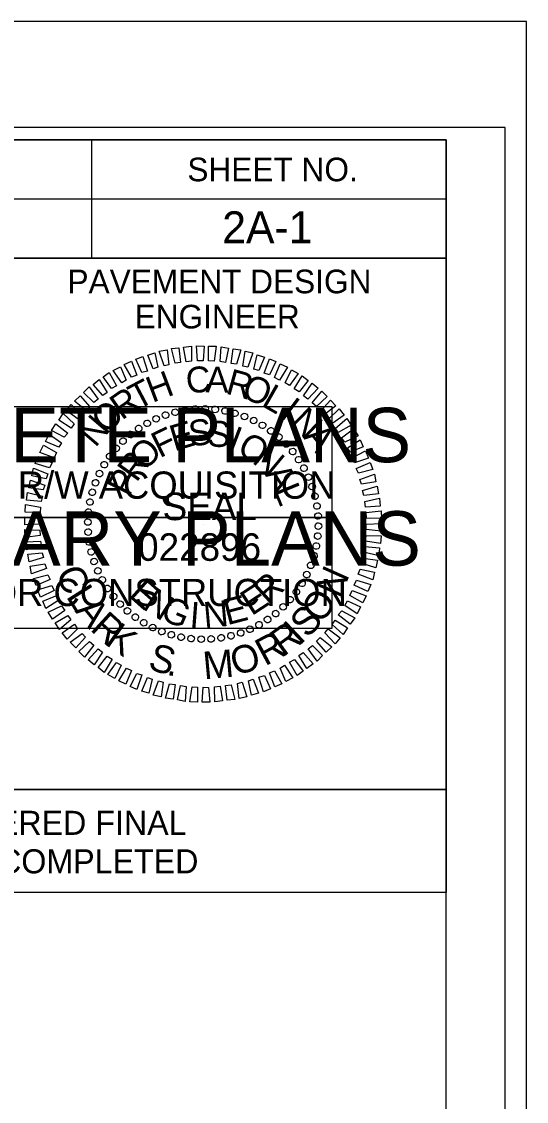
# Model space of a CAD drawing. Extents: x 1734085 to 1734267, y 541107 to 541226.
# Drawn here: x 1734254.98 to 1734266.51, y 541201.19 to 541225.88 of the extents above; entities that cross this region are included whole.
import ezdxf

# ---------------------------------------------------------------- set-up
doc = ezdxf.new("R2010")
doc.units = 0
for name, color, linetype in [('Sheet Cutting Line CELL', 7, 'Continuous'), ('Sheet Data Field CELL', 7, 'Continuous'), ('Sheet PE Seal Cell', 7, 'Continuous'), ('Sheet Plot Border Inside CELL', 7, 'Continuous'), ('Sheet Plot Border Outside CELL', 7, 'Continuous'), ('Sheet Sticker Exception Certification CELL', 7, 'Continuous'), ('Sheet Sticker Incomplete CELL', 7, 'Continuous'), ('Sheet Sticker Preliminary CELL', 7, 'Continuous'), ('Sheet Typical CELL', 7, 'Continuous')]:
    doc.layers.add(name, color=color, linetype=linetype)

msp = doc.modelspace()

# ---------------------------------------------------------------- linework, layer by layer
at = {"layer": 'Sheet Cutting Line CELL'}
msp.add_line((1734266.513, 541225.875), (1734084.641, 541225.875), dxfattribs=at)
at = {"layer": 'Sheet PE Seal Cell'}
for p, q in [((1734258.267, 541216.884), (1734258.267, 541216.884)), ((1734258.488, 541216.947), (1734258.488, 541216.947)), ((1734258.719, 541216.989), (1734258.719, 541216.989)), ((1734258.945, 541217.02), (1734258.945, 541217.02)), ((1734259.176, 541217.025), (1734259.176, 541217.025)), ((1734259.407, 541217.01), (1734259.407, 541217.01)), ((1734259.632, 541216.973), (1734259.632, 541216.973)), ((1734259.853, 541216.926), (1734259.853, 541216.926)), ((1734257.853, 541216.695), (1734257.853, 541216.695)), ((1734258.057, 541216.8), (1734258.057, 541216.8)), ((1734260.073, 541216.852), (1734260.073, 541216.852)), ((1734260.283, 541216.758), (1734260.283, 541216.758)), ((1734260.488, 541216.653), (1734260.488, 541216.653)), ((1734257.469, 541216.443), (1734257.469, 541216.443)), ((1734257.653, 541216.574), (1734257.653, 541216.574)), ((1734260.677, 541216.521), (1734260.677, 541216.521)), ((1734260.861, 541216.38), (1734260.861, 541216.38)), ((1734257.139, 541216.122), (1734257.139, 541216.122)), ((1734257.296, 541216.285), (1734257.296, 541216.285)), ((1734261.024, 541216.222), (1734261.024, 541216.222)), ((1734256.997, 541215.939), (1734256.997, 541215.939)), ((1734261.181, 541216.049), (1734261.181, 541216.049)), ((1734256.866, 541215.75), (1734256.866, 541215.75)), ((1734261.312, 541215.865), (1734261.312, 541215.865)), ((1734261.433, 541215.666), (1734261.433, 541215.666)), ((1734256.761, 541215.545), (1734256.761, 541215.545)), ((1734261.538, 541215.461), (1734261.538, 541215.461)), ((1734256.666, 541215.335), (1734256.666, 541215.335)), ((1734261.622, 541215.251), (1734261.622, 541215.251)), ((1734256.545, 541214.894), (1734256.545, 541214.894)), ((1734256.593, 541215.114), (1734256.593, 541215.114)), ((1734261.685, 541215.03), (1734261.685, 541215.03)), ((1734256.509, 541214.668), (1734256.509, 541214.668)), ((1734261.727, 541214.799), (1734261.727, 541214.799)), ((1734256.493, 541214.437), (1734256.493, 541214.437)), ((1734261.759, 541214.574), (1734261.759, 541214.574)), ((1734256.498, 541214.206), (1734256.498, 541214.206)), ((1734259.128, 541214.39), (1734259.128, 541214.39)), ((1734261.764, 541214.343), (1734261.764, 541214.343)), ((1734256.53, 541213.98), (1734256.53, 541213.98)), ((1734261.748, 541214.112), (1734261.748, 541214.112)), ((1734256.572, 541213.749), (1734256.572, 541213.749)), ((1734261.664, 541213.665), (1734261.664, 541213.665)), ((1734261.711, 541213.886), (1734261.711, 541213.886)), ((1734256.635, 541213.529), (1734256.635, 541213.529)), ((1734261.591, 541213.445), (1734261.591, 541213.445)), ((1734256.719, 541213.319), (1734256.719, 541213.319)), ((1734261.496, 541213.235), (1734261.496, 541213.235)), ((1734256.824, 541213.114), (1734256.824, 541213.114)), ((1734256.944, 541212.915), (1734256.944, 541212.915)), ((1734261.391, 541213.03), (1734261.391, 541213.03)), ((1734257.076, 541212.731), (1734257.076, 541212.731)), ((1734261.26, 541212.841), (1734261.26, 541212.841)), ((1734257.233, 541212.558), (1734257.233, 541212.558)), ((1734260.961, 541212.495), (1734260.961, 541212.495)), ((1734261.118, 541212.657), (1734261.118, 541212.657)), ((1734257.396, 541212.4), (1734257.396, 541212.4)), ((1734257.58, 541212.258), (1734257.58, 541212.258)), ((1734260.604, 541212.206), (1734260.604, 541212.206)), ((1734260.787, 541212.337), (1734260.787, 541212.337)), ((1734257.769, 541212.127), (1734257.769, 541212.127)), ((1734257.973, 541212.022), (1734257.973, 541212.022)), ((1734258.183, 541211.928), (1734258.183, 541211.928)), ((1734260.199, 541211.98), (1734260.199, 541211.98)), ((1734260.404, 541212.085), (1734260.404, 541212.085)), ((1734258.404, 541211.854), (1734258.404, 541211.854)), ((1734258.624, 541211.807), (1734258.624, 541211.807)), ((1734258.85, 541211.77), (1734258.85, 541211.77)), ((1734259.081, 541211.754), (1734259.081, 541211.754)), ((1734259.312, 541211.76), (1734259.312, 541211.76)), ((1734259.538, 541211.791), (1734259.538, 541211.791)), ((1734259.769, 541211.833), (1734259.769, 541211.833)), ((1734259.989, 541211.896), (1734259.989, 541211.896))]:
    msp.add_line(p, q, dxfattribs=at)
for points in [[(1734258.236, 541218.007), (1734258.126, 541218.338), (1734258.304, 541218.375), (1734258.346, 541218.033)], [(1734258.488, 541218.065), (1734258.404, 541218.401), (1734258.577, 541218.417), (1734258.614, 541218.081)], [(1734258.74, 541218.096), (1734258.682, 541218.432), (1734258.861, 541218.453), (1734258.866, 541218.112)], [(1734259.002, 541218.123), (1734258.976, 541218.464), (1734259.149, 541218.459), (1734259.128, 541218.117)], [(1734259.254, 541218.117), (1734259.254, 541218.459), (1734259.428, 541218.453), (1734259.38, 541218.112)], [(1734259.517, 541218.102), (1734259.538, 541218.443), (1734259.711, 541218.411), (1734259.643, 541218.081)], [(1734259.769, 541218.06), (1734259.816, 541218.396), (1734259.989, 541218.369), (1734259.895, 541218.044)], [(1734260.037, 541218.002), (1734260.089, 541218.343), (1734260.268, 541218.301), (1734260.147, 541217.976)], [(1734257.496, 541217.745), (1734257.328, 541218.039), (1734257.49, 541218.112), (1734257.611, 541217.792)], [(1734257.727, 541217.855), (1734257.59, 541218.159), (1734257.748, 541218.222), (1734257.858, 541217.886)], [(1734257.984, 541217.939), (1734257.863, 541218.254), (1734258.026, 541218.301), (1734258.094, 541217.976)], [(1734260.289, 541217.934), (1734260.367, 541218.259), (1734260.53, 541218.207), (1734260.399, 541217.897)], [(1734260.525, 541217.839), (1734260.646, 541218.17), (1734260.793, 541218.107), (1734260.646, 541217.802)], [(1734257.039, 541217.487), (1734256.845, 541217.755), (1734256.981, 541217.855), (1734257.154, 541217.55)], [(1734257.27, 541217.619), (1734257.076, 541217.902), (1734257.238, 541217.986), (1734257.37, 541217.682)], [(1734260.761, 541217.739), (1734260.892, 541218.049), (1734261.055, 541217.976), (1734260.877, 541217.682)], [(1734261.003, 541217.619), (1734261.144, 541217.918), (1734261.302, 541217.829), (1734261.102, 541217.556)], [(1734256.839, 541217.33), (1734256.614, 541217.582), (1734256.755, 541217.692), (1734256.939, 541217.398)], [(1734261.207, 541217.477), (1734261.391, 541217.781), (1734261.528, 541217.671), (1734261.323, 541217.414)], [(1734261.423, 541217.319), (1734261.617, 541217.608), (1734261.753, 541217.493), (1734261.522, 541217.246)], [(1734256.629, 541217.167), (1734256.398, 541217.398), (1734256.524, 541217.524), (1734256.729, 541217.241)], [(1734261.622, 541217.157), (1734261.837, 541217.43), (1734261.963, 541217.304), (1734261.722, 541217.078)], [(1734256.272, 541216.784), (1734255.999, 541216.989), (1734256.115, 541217.125), (1734256.346, 541216.878)], [(1734256.456, 541216.983), (1734256.188, 541217.199), (1734256.32, 541217.319), (1734256.54, 541217.067)], [(1734261.811, 541216.973), (1734262.037, 541217.22), (1734262.163, 541217.094), (1734261.89, 541216.889)], [(1734256.115, 541216.584), (1734255.831, 541216.763), (1734255.931, 541216.915), (1734256.183, 541216.684)], [(1734261.995, 541216.784), (1734262.236, 541217.02), (1734262.347, 541216.878), (1734262.068, 541216.679)], [(1734255.957, 541216.374), (1734255.663, 541216.532), (1734255.768, 541216.679), (1734256.041, 541216.469)], [(1734262.152, 541216.579), (1734262.41, 541216.8), (1734262.509, 541216.647), (1734262.215, 541216.479)], [(1734255.831, 541216.149), (1734255.532, 541216.28), (1734255.611, 541216.443), (1734255.894, 541216.248)], [(1734262.289, 541216.364), (1734262.567, 541216.563), (1734262.667, 541216.406), (1734262.362, 541216.259)], [(1734255.726, 541215.907), (1734255.401, 541216.028), (1734255.48, 541216.191), (1734255.779, 541216.023)], [(1734262.425, 541216.133), (1734262.719, 541216.317), (1734262.788, 541216.154), (1734262.488, 541216.033)], [(1734255.621, 541215.676), (1734255.296, 541215.771), (1734255.364, 541215.933), (1734255.679, 541215.786)], [(1734262.53, 541215.907), (1734262.84, 541216.065), (1734262.908, 541215.897), (1734262.583, 541215.792)], [(1734255.543, 541215.424), (1734255.217, 541215.492), (1734255.254, 541215.666), (1734255.585, 541215.534)], [(1734262.625, 541215.66), (1734262.945, 541215.797), (1734263.003, 541215.634), (1734262.677, 541215.55)], [(1734255.474, 541215.172), (1734255.149, 541215.214), (1734255.186, 541215.393), (1734255.516, 541215.282)], [(1734262.709, 541215.408), (1734263.045, 541215.529), (1734263.076, 541215.356), (1734262.746, 541215.298)], [(1734262.772, 541215.156), (1734263.103, 541215.256), (1734263.134, 541215.078), (1734262.803, 541215.046)], [(1734255.432, 541214.904), (1734255.096, 541214.936), (1734255.117, 541215.114), (1734255.459, 541215.03)], [(1734262.819, 541214.904), (1734263.16, 541214.978), (1734263.176, 541214.799), (1734262.84, 541214.778)], [(1734255.406, 541214.652), (1734255.065, 541214.663), (1734255.075, 541214.836), (1734255.417, 541214.778)], [(1734262.851, 541214.652), (1734263.192, 541214.694), (1734263.202, 541214.516), (1734262.861, 541214.526)], [(1734255.401, 541214.39), (1734255.06, 541214.374), (1734255.06, 541214.553), (1734255.401, 541214.516)], [(1734262.856, 541214.39), (1734263.197, 541214.406), (1734263.197, 541214.227), (1734262.856, 541214.264)], [(1734255.406, 541214.127), (1734255.065, 541214.085), (1734255.054, 541214.264), (1734255.396, 541214.253)], [(1734255.438, 541213.875), (1734255.096, 541213.802), (1734255.081, 541213.98), (1734255.417, 541214.001)], [(1734262.851, 541214.127), (1734263.192, 541214.117), (1734263.181, 541213.944), (1734262.84, 541214.001)], [(1734255.485, 541213.623), (1734255.154, 541213.524), (1734255.123, 541213.702), (1734255.453, 541213.734)], [(1734262.824, 541213.875), (1734263.16, 541213.844), (1734263.139, 541213.665), (1734262.798, 541213.749)], [(1734255.548, 541213.371), (1734255.212, 541213.251), (1734255.18, 541213.424), (1734255.511, 541213.482)], [(1734262.782, 541213.608), (1734263.108, 541213.566), (1734263.071, 541213.387), (1734262.74, 541213.497)], [(1734255.632, 541213.119), (1734255.312, 541212.983), (1734255.254, 541213.146), (1734255.579, 541213.23)], [(1734262.714, 541213.356), (1734263.04, 541213.287), (1734263.003, 541213.114), (1734262.672, 541213.245)], [(1734255.726, 541212.873), (1734255.417, 541212.715), (1734255.348, 541212.883), (1734255.674, 541212.988)], [(1734262.635, 541213.104), (1734262.961, 541213.009), (1734262.893, 541212.846), (1734262.578, 541212.993)], [(1734255.831, 541212.647), (1734255.537, 541212.463), (1734255.469, 541212.626), (1734255.768, 541212.747)], [(1734262.53, 541212.873), (1734262.856, 541212.752), (1734262.777, 541212.589), (1734262.478, 541212.757)], [(1734255.968, 541212.416), (1734255.69, 541212.216), (1734255.59, 541212.374), (1734255.894, 541212.521)], [(1734262.425, 541212.631), (1734262.725, 541212.5), (1734262.646, 541212.337), (1734262.362, 541212.531)], [(1734256.104, 541212.201), (1734255.847, 541211.98), (1734255.747, 541212.132), (1734256.041, 541212.3)], [(1734262.142, 541212.195), (1734262.425, 541212.017), (1734262.326, 541211.865), (1734262.074, 541212.096)], [(1734262.299, 541212.405), (1734262.593, 541212.248), (1734262.488, 541212.101), (1734262.215, 541212.311)], [(1734256.262, 541211.996), (1734256.02, 541211.76), (1734255.91, 541211.901), (1734256.188, 541212.101)], [(1734261.984, 541211.996), (1734262.257, 541211.791), (1734262.142, 541211.655), (1734261.911, 541211.901)], [(1734256.446, 541211.807), (1734256.22, 541211.56), (1734256.094, 541211.686), (1734256.367, 541211.891)], [(1734256.635, 541211.623), (1734256.419, 541211.35), (1734256.293, 541211.476), (1734256.535, 541211.702)], [(1734261.801, 541211.796), (1734262.068, 541211.581), (1734261.937, 541211.46), (1734261.717, 541211.712)], [(1734256.834, 541211.46), (1734256.64, 541211.172), (1734256.503, 541211.287), (1734256.734, 541211.534)], [(1734261.417, 541211.45), (1734261.643, 541211.198), (1734261.501, 541211.088), (1734261.318, 541211.382)], [(1734261.627, 541211.613), (1734261.858, 541211.382), (1734261.732, 541211.256), (1734261.528, 541211.539)], [(1734257.049, 541211.303), (1734256.866, 541210.998), (1734256.729, 541211.109), (1734256.934, 541211.366)], [(1734257.254, 541211.161), (1734257.112, 541210.862), (1734256.955, 541210.951), (1734257.154, 541211.224)], [(1734261.218, 541211.292), (1734261.412, 541211.025), (1734261.276, 541210.925), (1734261.102, 541211.229)], [(1734257.496, 541211.04), (1734257.364, 541210.731), (1734257.202, 541210.804), (1734257.38, 541211.098)], [(1734257.732, 541210.941), (1734257.611, 541210.61), (1734257.464, 541210.673), (1734257.611, 541210.977)], [(1734260.761, 541211.035), (1734260.929, 541210.741), (1734260.766, 541210.668), (1734260.646, 541210.988)], [(1734260.987, 541211.161), (1734261.181, 541210.878), (1734261.018, 541210.794), (1734260.887, 541211.098)], [(1734257.968, 541210.846), (1734257.889, 541210.521), (1734257.727, 541210.573), (1734257.858, 541210.883)], [(1734258.22, 541210.778), (1734258.168, 541210.437), (1734257.989, 541210.479), (1734258.11, 541210.804)], [(1734258.488, 541210.72), (1734258.441, 541210.384), (1734258.267, 541210.41), (1734258.362, 541210.736)], [(1734258.74, 541210.678), (1734258.719, 541210.337), (1734258.546, 541210.368), (1734258.614, 541210.699)], [(1734259.769, 541210.715), (1734259.853, 541210.379), (1734259.68, 541210.363), (1734259.643, 541210.699)], [(1734260.021, 541210.773), (1734260.131, 541210.442), (1734259.953, 541210.405), (1734259.911, 541210.746)], [(1734260.273, 541210.841), (1734260.394, 541210.526), (1734260.231, 541210.479), (1734260.163, 541210.804)], [(1734260.53, 541210.925), (1734260.667, 541210.62), (1734260.509, 541210.557), (1734260.399, 541210.893)], [(1734259.002, 541210.662), (1734259.002, 541210.321), (1734258.829, 541210.326), (1734258.876, 541210.668)], [(1734259.254, 541210.657), (1734259.281, 541210.316), (1734259.107, 541210.321), (1734259.128, 541210.662)], [(1734259.517, 541210.683), (1734259.575, 541210.347), (1734259.396, 541210.326), (1734259.391, 541210.668)]]:
    msp.add_lwpolyline(points, close=True, dxfattribs=at)
for centre, major_axis in [((1734258.057, 541216.796), (-0.0307, 0.0691)), ((1734258.271, 541216.88), (-0.0246, 0.0715)), ((1734258.491, 541216.945), (-0.0183, 0.0734)), ((1734258.716, 541216.991), (-0.0118, 0.0747)), ((1734258.945, 541217.017), (-0.0053, 0.0754)), ((1734259.174, 541217.023), (0.0013, 0.0756)), ((1734259.404, 541217.009), (0.0079, 0.0752)), ((1734259.631, 541216.975), (0.0144, 0.0742)), ((1734259.854, 541216.921), (0.0208, 0.0727)), ((1734260.072, 541216.848), (0.0271, 0.0706)), ((1734257.656, 541216.573), (-0.0423, 0.0627)), ((1734257.852, 541216.693), (-0.0367, 0.0661)), ((1734260.283, 541216.757), (0.0331, 0.0679)), ((1734260.485, 541216.647), (0.0389, 0.0648)), ((1734257.299, 541216.284), (-0.0525, 0.0544)), ((1734257.471, 541216.437), (-0.0476, 0.0588)), ((1734260.676, 541216.52), (0.0444, 0.0612)), ((1734260.856, 541216.377), (0.0496, 0.0571)), ((1734257.141, 541216.118), (-0.0571, 0.0496)), ((1734261.023, 541216.219), (0.0544, 0.0525)), ((1734261.175, 541216.047), (0.0588, 0.0476)), ((1734256.998, 541215.938), (-0.0612, 0.0444)), ((1734261.311, 541215.863), (0.0627, 0.0423)), ((1734256.761, 541215.544), (-0.0679, 0.0331)), ((1734256.871, 541215.746), (-0.0648, 0.0389)), ((1734261.431, 541215.667), (0.0661, 0.0367)), ((1734256.67, 541215.334), (-0.0706, 0.0271)), ((1734261.534, 541215.461), (0.0691, 0.0307)), ((1734256.597, 541215.116), (-0.0727, 0.0208)), ((1734261.618, 541215.247), (0.0715, 0.0246)), ((1734256.543, 541214.892), (-0.0742, 0.0144)), ((1734261.683, 541215.027), (0.0734, 0.0183)), ((1734256.509, 541214.665), (-0.0752, 0.0079)), ((1734261.729, 541214.802), (0.0747, 0.0118)), ((1734261.755, 541214.574), (0.0754, 0.0053)), ((1734256.495, 541214.436), (-0.0756, 0.0013)), ((1734261.761, 541214.344), (0.0756, -0.0013)), ((1734256.501, 541214.206), (-0.0754, -0.0053)), ((1734261.747, 541214.115), (0.0752, -0.0079)), ((1734256.527, 541213.978), (-0.0747, -0.0118)), ((1734261.713, 541213.888), (0.0742, -0.0144)), ((1734256.573, 541213.753), (-0.0734, -0.0183)), ((1734261.66, 541213.664), (0.0727, -0.0208)), ((1734256.638, 541213.533), (-0.0715, -0.0246)), ((1734261.587, 541213.446), (0.0706, -0.0271)), ((1734256.723, 541213.319), (-0.0691, -0.0307)), ((1734256.825, 541213.113), (-0.0661, -0.0367)), ((1734261.495, 541213.236), (0.0679, -0.0331)), ((1734256.945, 541212.917), (-0.0627, -0.0423)), ((1734261.259, 541212.842), (0.0612, -0.0444)), ((1734261.386, 541213.034), (0.0648, -0.0389)), ((1734257.082, 541212.733), (-0.0588, -0.0476)), ((1734261.116, 541212.662), (0.0571, -0.0496)), ((1734257.234, 541212.561), (-0.0544, -0.0525)), ((1734257.401, 541212.403), (-0.0496, -0.0571)), ((1734260.786, 541212.343), (0.0476, -0.0588)), ((1734260.958, 541212.496), (0.0525, -0.0544)), ((1734257.58, 541212.26), (-0.0444, -0.0612)), ((1734257.772, 541212.133), (-0.0389, -0.0648)), ((1734260.405, 541212.087), (0.0367, -0.0661)), ((1734260.601, 541212.207), (0.0423, -0.0627)), ((1734257.974, 541212.023), (-0.0331, -0.0679)), ((1734258.185, 541211.931), (-0.0271, -0.0706)), ((1734258.402, 541211.859), (-0.0208, -0.0727)), ((1734259.986, 541211.9), (0.0246, -0.0715)), ((1734260.199, 541211.984), (0.0307, -0.0691)), ((1734258.626, 541211.805), (-0.0144, -0.0742)), ((1734258.853, 541211.771), (-0.0079, -0.0752)), ((1734259.082, 541211.757), (-0.0013, -0.0756)), ((1734259.312, 541211.763), (0.0053, -0.0754)), ((1734259.54, 541211.789), (0.0118, -0.0747)), ((1734259.765, 541211.835), (0.0183, -0.0734))]:
    msp.add_ellipse(centre, major_axis=major_axis, ratio=0.999708, dxfattribs=at)
at = {"layer": 'Sheet Plot Border Inside CELL'}
msp.add_lwpolyline([(1734266.027, 541223.451), (1734086.045, 541223.451), (1734086.045, 541109.5), (1734266.027, 541109.5)], close=True, dxfattribs=at)
at = {"layer": 'Sheet Plot Border Outside CELL'}
msp.add_lwpolyline([(1734266.513, 541225.875), (1734084.641, 541225.875), (1734084.641, 541107.075), (1734266.513, 541107.075)], close=True, dxfattribs=at)
at = {"layer": 'Sheet Sticker Exception Certification CELL'}
for p, q in [((1734243.071, 541208.32), (1734264.677, 541208.32)), ((1734264.677, 541208.319), (1734264.677, 541205.969)), ((1734264.677, 541205.97), (1734243.071, 541205.97))]:
    msp.add_line(p, q, dxfattribs=at)
at = {"layer": 'Sheet Sticker Incomplete CELL'}
msp.add_lwpolyline([(1734246.196, 541214.54), (1734246.196, 541217.078), (1734262.072, 541217.078), (1734262.072, 541214.54)], close=True, dxfattribs=at)
at = {"layer": 'Sheet Sticker Preliminary CELL'}
msp.add_lwpolyline([(1734246.196, 541212.002), (1734246.196, 541214.54), (1734262.072, 541214.54), (1734262.072, 541212.002)], close=True, dxfattribs=at)
at = {"layer": 'Sheet Typical CELL'}
for p, q in [((1734256.577, 541223.17), (1734256.577, 541220.47)), ((1734243.071, 541221.82), (1734264.677, 541221.82))]:
    msp.add_line(p, q, dxfattribs=at)
for points in [[(1734264.677, 541223.175), (1734102.677, 541223.175), (1734102.677, 541109.775), (1734264.677, 541109.775)], [(1734243.071, 541223.175), (1734264.677, 541223.175), (1734264.677, 541220.47), (1734243.071, 541220.47)], [(1734253.877, 541220.47), (1734264.677, 541220.47), (1734264.677, 541208.32), (1734253.877, 541208.32)]]:
    msp.add_lwpolyline(points, close=True, dxfattribs=at)

# ---------------------------------------------------------------- texts
at = {"layer": 'Sheet Data Field CELL'}
msp.add_text('2A-1', height=0.729, dxfattribs=at).set_placement((1734259.566, 541220.81))
at = {"layer": 'Sheet PE Seal Cell'}
for s, height, rotation, p in [('H', 0.592, 20.6195, (1734257.968, 541217.157)), ('C', 0.592, 6.2199, (1734258.766, 541217.367)), ('A', 0.592, 359.0203, (1734259.181, 541217.398)), ('R', 0.592, 344.6211, (1734259.622, 541217.377)), ('T', 0.592, 27.8198, (1734257.627, 541216.983)), ('O', 0.592, 337.4212, (1734259.974, 541217.298)), ('R', 0.592, 35.0205, (1734257.27, 541216.752)), ('L', 0.592, 330.2209, (1734260.436, 541217.104)), ('O', 0.592, 42.2217, (1734256.908, 541216.427)), ('I', 0.592, 323.0201, (1734260.861, 541216.852)), ('N', 0.592, 49.4235, (1734256.666, 541216.122)), ('N', 0.592, 315.8189, (1734261.087, 541216.689)), ('F', 0.592, 25.967, (1734258.136, 541215.891)), ('E', 0.592, 16.6111, (1734258.472, 541216.049)), ('S', 0.592, 7.2556, (1734258.834, 541216.159)), ('S', 0.592, 357.9004, (1734259.212, 541216.164)), ('I', 0.592, 339.1896, (1734259.664, 541216.091)), ('O', 0.592, 329.8335, (1734259.874, 541216.017)), ('A', 0.592, 308.6172, (1734261.396, 541216.38)), ('O', 0.592, 44.6812, (1734257.79, 541215.582)), ('N', 0.592, 320.4766, (1734260.226, 541215.807)), ('R', 0.592, 54.0397, (1734257.606, 541215.324)), ('P', 0.592, 63.3989, (1734257.438, 541214.988)), ('A', 0.592, 301.7603, (1734260.525, 541215.534)), ('L', 0.592, 292.4008, (1734260.73, 541215.172)), ('SEAL', 0.6298, 360, (1734258.204, 541214.479)), ('C', 0.63, 292.9481, (1734255.754, 541213.283)), ('N', 0.63, 65.9082, (1734262.238, 541212.675)), ('R', 0.592, 42.4814, (1734260.609, 541212.526)), ('L', 0.63, 302.5303, (1734255.986, 541212.737)), ('E', 0.592, 318.2769, (1734257.406, 541212.747)), ('N', 0.592, 327.634, (1734257.721, 541212.463)), ('E', 0.592, 33.1241, (1734260.236, 541212.279)), ('G', 0.592, 336.9902, (1734258.12, 541212.227)), ('E', 0.592, 14.4118, (1734259.68, 541212.075)), ('O', 0.63, 54.3478, (1734261.831, 541212.087)), ('A', 0.63, 308.805, (1734256.185, 541212.403)), ('I', 0.592, 355.7012, (1734258.808, 541212.027)), ('N', 0.592, 5.0564, (1734259.16, 541212.012)), ('S', 0.63, 47.0221, (1734261.515, 541211.761)), ('R', 0.63, 317.6453, (1734256.526, 541211.974)), ('I', 0.63, 43.2201, (1734261.336, 541211.609)), ('K', 0.63, 325.1256, (1734256.862, 541211.656)), ('R', 0.63, 35.7399, (1734260.955, 541211.345)), ('R', 0.63, 28.2596, (1734260.543, 541211.133)), ('S', 0.63, 343.6099, (1734257.846, 541211.079)), ('M', 0.63, 5.1697, (1734259.152, 541210.839)), ('O', 0.63, 16.6992, (1734259.862, 541210.916)), ('.', 0.63, 350.9356, (1734258.279, 541210.942))]:
    msp.add_text(s, height=height, rotation=rotation, dxfattribs=at).set_placement(p)
msp.add_text('022896', height=0.6298, dxfattribs=at).set_placement((1734257.644, 541213.549))
at = {"layer": 'Sheet Sticker Exception Certification CELL'}
for s, p in [('DOCUMENT NOT CONSIDERED FINAL', (1734245.347, 541207.285)), ('UNLESS ALL SIGNATURES COMPLETED', (1734244.799, 541206.405))]:
    msp.add_text(s, height=0.55, dxfattribs=at).set_placement(p)
at = {"layer": 'Sheet Sticker Incomplete CELL'}
for s, height, p in [('INCOMPLETE PLANS', 1.24416, (1734247.146, 541215.803)), ('DO NOT USE FOR R/W ACQUISITION', 0.62208, (1734247.502, 541214.969))]:
    msp.add_text(s, height=height, dxfattribs=at).set_placement(p)
at = {"layer": 'Sheet Sticker Preliminary CELL'}
for s, height, p in [('PRELIMINARY PLANS', 1.24416, (1734246.906, 541213.439)), ('DO NOT USE FOR CONSTRUCTION', 0.62208, (1734248.316, 541212.515))]:
    msp.add_text(s, height=height, dxfattribs=at).set_placement(p)
at = {"layer": 'Sheet Typical CELL'}
for s, height, p in [('SHEET NO.', 0.54, (1734258.769, 541222.225)), ('PAVEMENT DESIGN', 0.54001, (1734256.031, 541219.665)), ('ENGINEER', 0.54, (1734257.565, 541218.861))]:
    msp.add_text(s, height=height, dxfattribs=at).set_placement(p)

doc.saveas('drawing.dxf')
